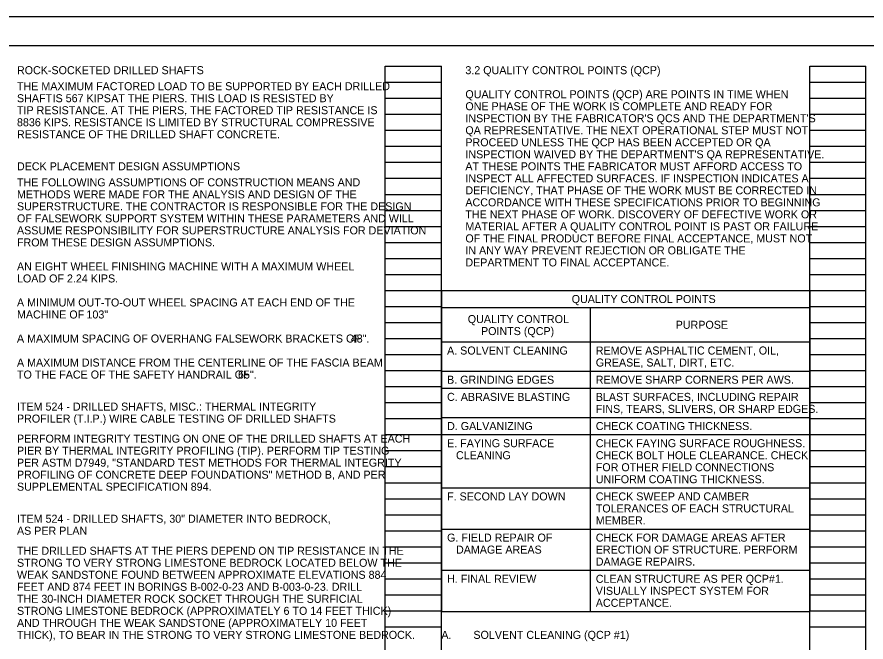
# Model space of a CAD drawing. Extents: x 0 to 45.3, y 0 to 22.
# Drawn here: x 9.82 to 24.66, y 11.07 to 22 of the extents above; entities that cross this region are included whole.
import ezdxf

# ---------------------------------------------------------------- set-up
doc = ezdxf.new("R2010")
doc.units = 0
for name, color, linetype in [('BR_P_Gen_Text', 7, 'Continuous'), ('SH_Border', 7, 'Continuous'), ('SH_Cut_Line', 7, 'Continuous'), ('SH_Data', 7, 'Continuous'), ('SH_Text', 7, 'Continuous')]:
    doc.layers.add(name, color=color, linetype=linetype)

msp = doc.modelspace()

# ---------------------------------------------------------------- linework, layer by layer
at = {"layer": 'BR_P_Gen_Text'}
for p, q in [((17.24, 17.22), (17.24, 11.61)), ((17.24, 17.22), (23.68, 17.22)), ((23.68, 17.22), (23.68, 11.61)), ((17.24, 16.92), (23.68, 16.92)), ((19.84, 16.92), (19.84, 11.61)), ((17.24, 16.32), (23.68, 16.32)), ((17.24, 15.81), (23.68, 15.81)), ((17.24, 15.51), (23.68, 15.51)), ((17.24, 15), (23.68, 15)), ((17.24, 14.7), (23.68, 14.7)), ((17.24, 13.77), (23.68, 13.77)), ((17.24, 13.05), (23.68, 13.05)), ((17.24, 12.33), (23.68, 12.33)), ((17.24, 11.61), (23.68, 11.61))]:
    msp.add_line(p, q, dxfattribs=at)
at = {"layer": 'SH_Border'}
msp.add_lwpolyline([(1.5, 21.5), (33.5, 21.5), (33.5, 0.5), (1.5, 0.5)], close=True, dxfattribs=at)
at = {"layer": 'SH_Cut_Line'}
msp.add_lwpolyline([(0, 0), (34, 0), (34, 22), (0, 22)], close=True, dxfattribs=at)
at = {"layer": 'SH_Data'}
for p, q in [((16.26, 0.98), (16.26, 21.14)), ((16.26, 21.14), (17.24, 21.14)), ((17.24, 0.98), (17.24, 21.14)), ((23.68, 0.98), (23.68, 21.14)), ((23.68, 21.14), (24.66, 21.14)), ((24.66, 0.98), (24.66, 21.14)), ((16.26, 20.86), (17.24, 20.86)), ((23.68, 20.86), (24.66, 20.86)), ((16.26, 20.58), (17.24, 20.58)), ((23.68, 20.58), (24.66, 20.58)), ((16.26, 20.3), (17.24, 20.3)), ((23.68, 20.3), (24.66, 20.3)), ((16.26, 20.02), (17.24, 20.02)), ((23.68, 20.02), (24.66, 20.02)), ((16.26, 19.74), (17.24, 19.74)), ((23.68, 19.74), (24.66, 19.74)), ((16.26, 19.46), (17.24, 19.46)), ((23.68, 19.46), (24.66, 19.46)), ((16.26, 19.18), (17.24, 19.18)), ((23.68, 19.18), (24.66, 19.18)), ((16.26, 18.9), (17.24, 18.9)), ((23.68, 18.9), (24.66, 18.9)), ((16.26, 18.62), (17.24, 18.62)), ((23.68, 18.62), (24.66, 18.62)), ((16.26, 18.34), (17.24, 18.34)), ((23.68, 18.34), (24.66, 18.34)), ((16.26, 18.06), (17.24, 18.06)), ((23.68, 18.06), (24.66, 18.06)), ((16.26, 17.78), (17.24, 17.78)), ((23.68, 17.78), (24.66, 17.78)), ((16.26, 17.5), (17.24, 17.5)), ((23.68, 17.5), (24.66, 17.5)), ((16.26, 17.22), (17.24, 17.22)), ((23.68, 17.22), (24.66, 17.22)), ((16.26, 16.94), (17.24, 16.94)), ((23.68, 16.94), (24.66, 16.94)), ((16.26, 16.66), (17.24, 16.66)), ((23.68, 16.66), (24.66, 16.66)), ((16.26, 16.38), (17.24, 16.38)), ((23.68, 16.38), (24.66, 16.38)), ((16.26, 16.1), (17.24, 16.1)), ((23.68, 16.1), (24.66, 16.1)), ((16.26, 15.82), (17.24, 15.82)), ((23.68, 15.82), (24.66, 15.82)), ((16.26, 15.54), (17.24, 15.54)), ((23.68, 15.54), (24.66, 15.54)), ((16.26, 15.26), (17.24, 15.26)), ((23.68, 15.26), (24.66, 15.26)), ((16.26, 14.98), (17.24, 14.98)), ((23.68, 14.98), (24.66, 14.98)), ((16.26, 14.7), (17.24, 14.7)), ((23.68, 14.7), (24.66, 14.7)), ((16.26, 14.42), (17.24, 14.42)), ((23.68, 14.42), (24.66, 14.42)), ((16.26, 14.14), (17.24, 14.14)), ((23.68, 14.14), (24.66, 14.14)), ((16.26, 13.86), (17.24, 13.86)), ((23.68, 13.86), (24.66, 13.86)), ((16.26, 13.58), (17.24, 13.58)), ((23.68, 13.58), (24.66, 13.58)), ((16.26, 13.3), (17.24, 13.3)), ((23.68, 13.3), (24.66, 13.3)), ((16.26, 13.02), (17.24, 13.02)), ((23.68, 13.02), (24.66, 13.02)), ((16.26, 12.74), (17.24, 12.74)), ((23.68, 12.74), (24.66, 12.74)), ((16.26, 12.46), (17.24, 12.46)), ((23.68, 12.46), (24.66, 12.46)), ((16.26, 12.18), (17.24, 12.18)), ((23.68, 12.18), (24.66, 12.18)), ((16.26, 11.9), (17.24, 11.9)), ((23.68, 11.9), (24.66, 11.9)), ((16.26, 11.62), (17.24, 11.62)), ((23.68, 11.62), (24.66, 11.62)), ((16.26, 11.34), (17.24, 11.34)), ((23.68, 11.34), (24.66, 11.34))]:
    msp.add_line(p, q, dxfattribs=at)

# ---------------------------------------------------------------- texts
at = {"layer": 'BR_P_Gen_Text'}
for s, p in [('3.2 QUALITY CONTROL POINTS (QCP) ', (17.66, 21)), ('QUALITY CONTROL POINTS (QCP) ARE POINTS IN TIME WHEN ', (17.66, 20.58)), ('ONE PHASE OF THE WORK IS COMPLETE AND READY FOR ', (17.66, 20.37)), ("INSPECTION BY THE FABRICATOR'S QCS AND THE DEPARTMENT'S ", (17.66, 20.16)), ('QA REPRESENTATIVE. THE NEXT OPERATIONAL STEP MUST NOT ', (17.66, 19.95)), ('PROCEED UNLESS THE QCP HAS BEEN ACCEPTED OR QA ', (17.66, 19.74)), ("INSPECTION WAIVED BY THE DEPARTMENT'S QA REPRESENTATIVE. ", (17.66, 19.53)), ('AT THESE POINTS THE FABRICATOR MUST AFFORD ACCESS TO ', (17.66, 19.32)), ('INSPECT ALL AFFECTED SURFACES. IF INSPECTION INDICATES A ', (17.66, 19.11)), ('DEFICIENCY, THAT PHASE OF THE WORK MUST BE CORRECTED IN ', (17.66, 18.9)), ('ACCORDANCE WITH THESE SPECIFICATIONS PRIOR TO BEGINNING ', (17.66, 18.69)), ('THE NEXT PHASE OF WORK. DISCOVERY OF DEFECTIVE WORK OR ', (17.66, 18.48)), ('MATERIAL AFTER A QUALITY CONTROL POINT IS PAST OR FAILURE ', (17.66, 18.27)), ('OF THE FINAL PRODUCT BEFORE FINAL ACCEPTANCE, MUST NOT ', (17.66, 18.06)), ('IN ANY WAY PREVENT REJECTION OR OBLIGATE THE ', (17.66, 17.85)), ('DEPARTMENT TO FINAL ACCEPTANCE. ', (17.66, 17.64)), ('QUALITY CONTROL POINTS', (19.519, 17)), ('QUALITY CONTROL', (17.702, 16.65)), ('PURPOSE', (21.337, 16.55)), ('POINTS (QCP)', (17.933, 16.44)), ('A. SOLVENT CLEANING', (17.34, 16.1)), ('REMOVE ASPHALTIC CEMENT, OIL, ', (19.94, 16.1)), ('GREASE, SALT, DIRT, ETC.', (19.94, 15.89)), ('B. GRINDING EDGES', (17.34, 15.59)), ('REMOVE SHARP CORNERS PER AWS.', (19.94, 15.59)), ('C. ABRASIVE BLASTING', (17.34, 15.29)), ('BLAST SURFACES, INCLUDING REPAIR ', (19.94, 15.29)), ('FINS, TEARS, SLIVERS, OR SHARP EDGES.', (19.94, 15.08)), ('D. GALVANIZING', (17.34, 14.78)), ('CHECK COATING THICKNESS.', (19.94, 14.78)), ('E. FAYING SURFACE', (17.34, 14.48)), ('CHECK FAYING SURFACE ROUGHNESS. ', (19.94, 14.48)), ('   CLEANING', (17.34, 14.27)), ('CHECK BOLT HOLE CLEARANCE. CHECK ', (19.94, 14.27)), ('FOR OTHER FIELD CONNECTIONS ', (19.94, 14.06)), ('UNIFORM COATING THICKNESS.', (19.94, 13.85)), ('F. SECOND LAY DOWN', (17.34, 13.55)), ('CHECK SWEEP AND CAMBER ', (19.94, 13.55)), ('TOLERANCES OF EACH STRUCTURAL ', (19.94, 13.34)), ('MEMBER.', (19.94, 13.13)), ('G. FIELD REPAIR OF', (17.34, 12.83)), ('CHECK FOR DAMAGE AREAS AFTER ', (19.94, 12.83)), ('   DAMAGE AREAS', (17.34, 12.62)), ('ERECTION OF STRUCTURE. PERFORM ', (19.94, 12.62)), ('DAMAGE REPAIRS.', (19.94, 12.41)), ('H. FINAL REVIEW', (17.34, 12.11)), ('CLEAN STRUCTURE AS PER QCP#1. ', (19.94, 12.11)), ('VISUALLY INSPECT SYSTEM FOR ', (19.94, 11.9)), ('ACCEPTANCE.', (19.94, 11.69)), ('A.', (17.24, 11.13)), ('SOLVENT CLEANING (QCP #1) ', (17.8, 11.13))]:
    msp.add_text(s, height=0.14, dxfattribs=at).set_placement(p)
at = {"layer": 'SH_Text'}
for s, p in [('ROCK-SOCKETED DRILLED SHAFTS', (9.82, 21)), ('THE MAXIMUM FACTORED LOAD TO BE SUPPORTED BY EACH DRILLED', (9.82, 20.72)), ('SHAFT ', (9.82, 20.51)), ('IS 567 KIPS ', (10.443, 20.51)), ('AT THE PIERS. THIS LOAD IS RESISTED BY', (11.468, 20.51)), ('TIP RESISTANCE. AT THE PIERS, THE FACTORED TIP RESISTANCE IS ', (9.82, 20.3)), ('8836 KIPS. RESISTANCE IS LIMITED BY STRUCTURAL COMPRESSIVE', (9.82, 20.09)), ('RESISTANCE OF THE DRILLED SHAFT CONCRETE.', (9.82, 19.88)), ('DECK PLACEMENT DESIGN ASSUMPTIONS', (9.82, 19.32)), ('THE FOLLOWING ASSUMPTIONS OF CONSTRUCTION MEANS AND', (9.82, 19.04)), ('METHODS WERE MADE FOR THE ANALYSIS AND DESIGN OF THE', (9.82, 18.83)), ('SUPERSTRUCTURE. THE CONTRACTOR IS RESPONSIBLE FOR THE DESIGN', (9.82, 18.62)), ('OF FALSEWORK SUPPORT SYSTEM WITHIN THESE PARAMETERS AND WILL', (9.82, 18.41)), ('ASSUME RESPONSIBILITY FOR SUPERSTRUCTURE ANALYSIS FOR DEVIATION', (9.82, 18.2)), ('FROM THESE DESIGN ASSUMPTIONS.', (9.82, 17.99)), ('AN EIGHT WHEEL FINISHING MACHINE WITH A MAXIMUM WHEEL', (9.82, 17.57)), ('LOAD OF 2.24 KIPS.', (9.82, 17.36)), ('A MINIMUM OUT-TO-OUT WHEEL SPACING AT EACH END OF THE ', (9.82, 16.94)), ('MACHINE OF ', (9.82, 16.73)), ('103"', (11.035, 16.73)), ('A MAXIMUM SPACING OF OVERHANG FALSEWORK BRACKETS OF ', (9.82, 16.31)), ('48".', (15.656, 16.31)), ('A MAXIMUM DISTANCE FROM THE CENTERLINE OF THE FASCIA BEAM', (9.82, 15.89)), ('TO THE FACE OF THE SAFETY HANDRAIL OF ', (9.82, 15.68)), ('65".', (13.685, 15.68)), ('ITEM 524 - DRILLED SHAFTS, MISC.: THERMAL INTEGRITY', (9.82, 15.12)), ('PROFILER (T.I.P.) WIRE CABLE TESTING OF DRILLED SHAFTS', (9.82, 14.91)), ('PERFORM INTEGRITY TESTING ON ONE OF THE DRILLED SHAFTS AT EACH', (9.82, 14.56)), ('PIER BY THERMAL INTEGRITY PROFILING (TIP). PERFORM TIP TESTING ', (9.82, 14.35)), ('PER ASTM D7949, "STANDARD TEST METHODS FOR THERMAL INTEGRITY ', (9.82, 14.14)), ('PROFILING OF CONCRETE DEEP FOUNDATIONS" METHOD B, AND PER ', (9.82, 13.93)), ('SUPPLEMENTAL SPECIFICATION 894.', (9.82, 13.72)), ('ITEM 524 - DRILLED SHAFTS, 30" DIAMETER INTO BEDROCK,', (9.82, 13.16)), ('AS PER PLAN', (9.82, 12.95)), ('THE DRILLED SHAFTS AT THE PIERS DEPEND ON TIP RESISTANCE IN THE ', (9.82, 12.6)), ('STRONG TO VERY STRONG LIMESTONE BEDROCK LOCATED BELOW THE ', (9.82, 12.39)), ('WEAK SANDSTONE FOUND BETWEEN APPROXIMATE ELEVATIONS 884 ', (9.82, 12.18)), ('FEET AND 874 FEET IN BORINGS B-002-0-23 AND B-003-0-23. DRILL ', (9.82, 11.97)), ('THE 30-INCH DIAMETER ROCK SOCKET THROUGH THE SURFICIAL ', (9.82, 11.76)), ('STRONG LIMESTONE BEDROCK (APPROXIMATELY 6 TO 14 FEET THICK) ', (9.82, 11.55)), ('AND THROUGH THE WEAK SANDSTONE (APPROXIMATELY 10 FEET ', (9.82, 11.34)), ('THICK), TO BEAR IN THE STRONG TO VERY STRONG LIMESTONE BEDROCK.', (9.82, 11.13))]:
    msp.add_text(s, height=0.14, dxfattribs=at).set_placement(p)

doc.saveas('drawing.dxf')
